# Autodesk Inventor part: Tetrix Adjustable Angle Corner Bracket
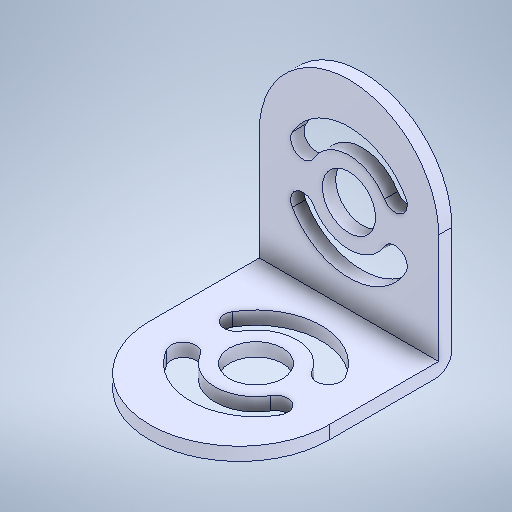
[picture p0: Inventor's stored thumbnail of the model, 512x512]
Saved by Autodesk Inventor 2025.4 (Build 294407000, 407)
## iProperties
Created: 2021-10
Part Number: Tetrix Adjustable Angle Corner Bracket
Material: Genérico
Document SubType Name: Modeling
Designer: usuario
Density: 1 g/cm^3
Appearance: Valor por defecto
Author: usuario
Sending System: SolidWorks 2016
Last Author: LENOVO
Last Saved: 2021-10-26
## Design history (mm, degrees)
fillet "Fillet1"
node "Sólido1"
